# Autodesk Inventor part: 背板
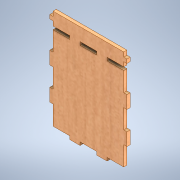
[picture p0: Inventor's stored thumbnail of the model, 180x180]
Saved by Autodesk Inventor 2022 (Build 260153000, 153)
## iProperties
Created: 2024-11
Part Number: 背板
Material: MDF 中密度繊維ボード
Document SubType Name: Modeling
Designer: shimizu
Density: 0.8 g/cm^3
Appearance: サクラ材 - ナチュラル 抑えた光沢
Author: shimizu
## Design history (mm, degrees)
sketch "スケッチ1"
  geometry: L1 (-32.841, 27.318)-(22.159, 27.318); L2 (-11.841, 17.318)-(-11.841, 14.818); L3 (-11.841, 14.818)-(-19.841, 14.818); L4 (-19.841, 14.818)-(-19.841, 17.318); L5 (9.159, 17.318)-(9.159, 14.818); L6 (9.159, 14.818)-(1.159, 14.818); L7 (1.159, 14.818)-(1.159, 17.318); L8 (-32.841, 23.818)-(-35.341, 23.818); L9 (-35.341, 23.818)-(-35.341, 20.818); L10 (-35.341, 20.818)-(-32.841, 20.818); L11 (22.159, 23.818)-(24.659, 23.818); L12 (24.659, 23.818)-(24.659, 20.818); L13 (24.659, 20.818)-(22.159, 20.818); L14 (-32.841, 17.318)-(-32.841, 20.818); L15 (-32.841, 23.818)-(-32.841, 27.318); L16 (22.159, 27.318)-(22.159, 23.818); L17 (22.159, 20.818)-(22.159, 17.318); L18 (22.159, 17.318)-(9.159, 17.318); L19 (1.159, 17.318)-(-11.841, 17.318); L20 (-19.841, 17.318)-(-32.841, 17.318); L21 (-32.841, 14.818)-(22.159, 14.818); L22 (22.159, 14.818)-(22.159, -50.182); L23 (22.159, -50.182)-(-32.841, -50.182); L24 (-32.841, -50.182)-(-32.841, 14.818); L25 (22.159, -0.182)-(24.659, -0.182); L26 (24.659, -0.182)-(24.659, -10.182); L27 (24.659, -10.182)-(22.159, -10.182); L28 (22.159, -10.182)-(22.159, -0.182); L29 (22.159, -25.182)-(24.659, -25.182); L30 (24.659, -25.182)-(24.659, -35.182); L31 (24.659, -35.182)-(22.159, -35.182); L32 (22.159, -35.182)-(22.159, -25.182); L33 (-32.841, -0.182)-(-35.341, -0.182); L34 (-35.341, -0.182)-(-35.341, -10.182); L35 (-35.341, -10.182)-(-32.841, -10.182); L36 (-32.841, -10.182)-(-32.841, -0.182); L37 (-32.841, -25.182)-(-35.341, -25.182); L38 (-35.341, -25.182)-(-35.341, -35.182); L39 (-35.341, -35.182)-(-32.841, -35.182); L40 (-32.841, -35.182)-(-32.841, -25.182); L41 (-19.841, -50.182)-(-11.841, -50.182); L42 (-11.841, -50.182)-(-11.841, -52.682); L43 (-11.841, -52.682)-(-19.841, -52.682); L44 (-19.841, -52.682)-(-19.841, -50.182); L45 (1.159, -50.182)-(9.159, -50.182); L46 (9.159, -50.182)-(9.159, -52.682); L47 (9.159, -52.682)-(1.159, -52.682); L48 (1.159, -52.682)-(1.159, -50.182); 11 further points
  constraints: 96 end point, 25 parallel, 11 perpendicular, 10 horizontal, 7 point on line
  dimensions: "d16" = 13 distance of L17.end L5.start; "d17" = 13 distance of L4.end L14.start; "d18" = 8 distance of L5.end L6.end; "d19" = 8 distance of L2.end L3.end; "d20" = 13 distance of L7.end L2.start; "d21" = 55 distance between parallel lines of L16 L15; "d22" = 60 distance between parallel lines of L12 L9; "d23" = 65 distance between parallel lines of L23 L21; "d24" = 55 distance between parallel lines of L22 L24; "d25" = 10 distance between parallel lines of L27 L25; "d26" = 10 distance between parallel lines of L31 L29; "d27" = 10 distance between parallel lines of L35 L33; "d28" = 10 distance between parallel lines of L39 L37; "d29" = 15 distance between parallel lines of L31 L23; "d30" = 15 distance between parallel lines of L27 L29; "d31" = 15 distance between parallel lines of L39 L23; "d32" = 15 distance between parallel lines of L35 L37; "d33" = 2.5 distance between parallel lines of L22 L26; "d34" = 2.5 distance between parallel lines of L32 L30; "d35" = 2.5 distance between parallel lines of L36 L34; "d36" = 2.5 distance between parallel lines of L38 L24; "d37" = 2.5 distance of L43.end L41.start; "d38" = 2.5 distance of L45.end L46.end
extrude "押し出し1" new body sketch "スケッチ1" distance "d14" = 2.5; taper "d15" = 0 deg
node "ソリッド1"
